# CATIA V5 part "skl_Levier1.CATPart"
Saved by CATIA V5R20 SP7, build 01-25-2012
Part number: skl_Levier1
Publications: "Plan.1", "Point.1", "Point.3", "Axe_LevierBati", "Axe_LevierBielles"
Bounding box of the stored display mesh (mm): x 0 to 20, y 0 to 82, z 152 to 152
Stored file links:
  J:\ACHTUNG2\skl_Levier1.CATPart
  J:\cmilovidofIAO\skl_IAO.CATProduct
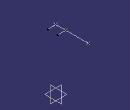
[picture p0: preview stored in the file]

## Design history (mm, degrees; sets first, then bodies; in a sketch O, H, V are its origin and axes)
Set1
  Point1: linked copy from another document
  Point2: linked copy from another document
  Plane1: linked copy from another document
  Point3: linked copy from another document
Body1 (main body)
  Line1 "7-13": type PtPt, FirstPoint Point1, SecondPoint Point2
  Line2 "Axe_LevierBati": type Normal, RefPoint Point3, RefSkin Plane1, Start 0, End 20
  Line3 "Axe_LevierBielles": type Normal, RefPoint Point1, RefSkin Plane1, Start 0, End 20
